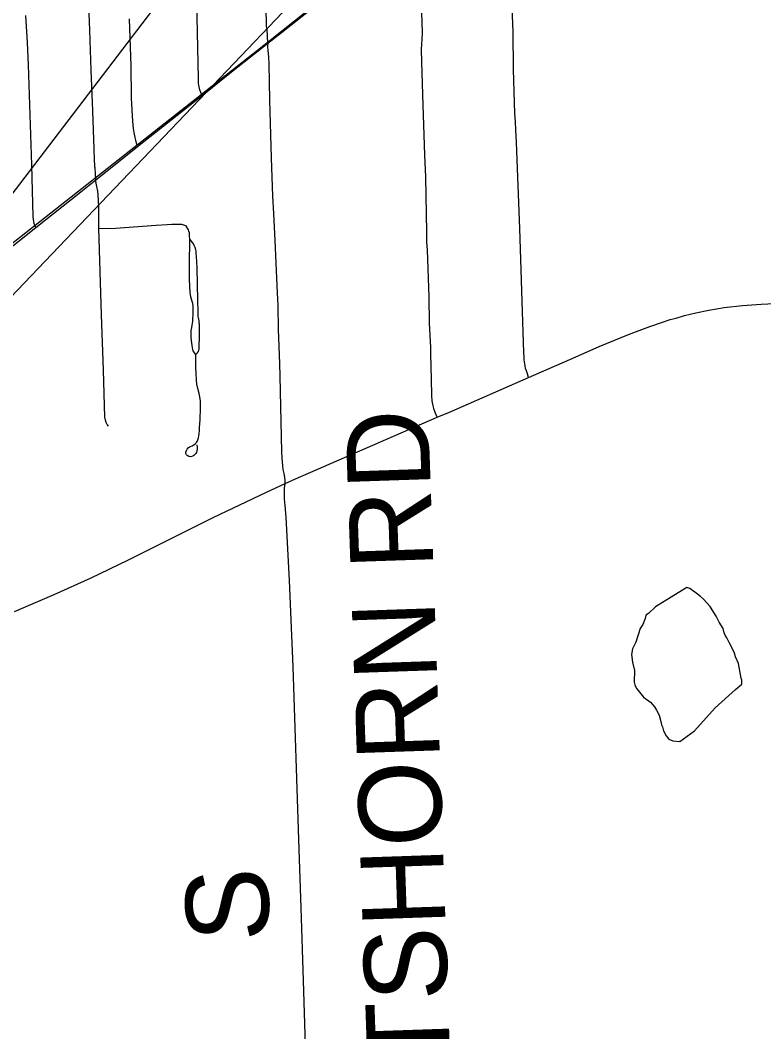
# Model space of a CAD drawing. Extents: x -12 to 34, y 0 to 22.
# Drawn here: x 5.489 to 5.999, y 17.363 to 18.055 of the extents above; entities that cross this region are included whole.
import ezdxf

# ---------------------------------------------------------------- set-up
doc = ezdxf.new("R2010")
doc.units = 0
for name, color, linetype in [('GM_X_Adjacent_County', 7, 'Continuous'), ('GM_X_Corporation', 7, 'Continuous'), ('GM_X_County_Road_Text', 7, 'Continuous'), ('GM_X_Major_Lake', 7, 'Continuous'), ('GM_X_Major_River', 7, 'Continuous'), ('GM_X_Minor_Lake', 7, 'Continuous'), ('GM_X_Township', 7, 'Continuous')]:
    doc.layers.add(name, color=color, linetype=linetype)

msp = doc.modelspace()

# ---------------------------------------------------------------- linework, layer by layer
at = {"layer": 'GM_X_Adjacent_County'}
msp.add_lwpolyline([(6.62656, 19.06353), (5.2189, 17.58992), (6.62656, 19.43297)], close=True, dxfattribs=at)
msp.add_lwpolyline([(6.62656, 19.06353), (5.2189, 17.58992), (6.62656, 19.43297)], dxfattribs=at)
at = {"layer": 'GM_X_Corporation'}
msp.add_lwpolyline([(4.21516, 16.89608), (4.31222, 16.96474), (4.74688, 17.31604), (5.03809, 17.55354), (5.18709, 17.66982), (5.65945, 18.04091), (6.05453, 18.35511), (6.09781, 18.38665), (6.1312, 18.40211), (6.16953, 18.40953), (6.55349, 18.44232), (6.69012, 18.44788), (6.85026, 18.4485), (6.9294, 18.45221), (7.10746, 18.45407), (7.25585, 18.4584), (7.28615, 18.45159), (7.37827, 18.44726), (7.7344, 18.45716)], dxfattribs=at)
at = {"layer": 'GM_X_Major_Lake'}
msp.add_lwpolyline([(5.48538, 17.65081), (5.51247, 17.66238), (5.53791, 17.6739), (5.56308, 17.68603), (5.6215, 17.71513), (5.65797, 17.73256), (5.67079, 17.73837), (5.6778, 17.74155), (5.77495, 17.7837), (5.78329, 17.78732), (5.83754, 17.811), (5.86588, 17.82338), (5.88581, 17.83215), (5.90598, 17.8404), (5.92058, 17.84578), (5.92934, 17.84893), (5.93456, 17.85054), (5.93854, 17.85166), (5.94425, 17.85328), (5.95207, 17.85526), (5.96089, 17.857), (5.97145, 17.85875), (5.98399, 17.86012), (5.99673, 17.86113), (6.01539, 17.86198)], dxfattribs=at)
at = {"layer": 'GM_X_Major_River'}
for points in [[(5.6138, 18.004), (5.613, 18.00601), (5.61224, 18.0079), (5.61179, 18.00994), (5.61148, 18.01213), (5.61133, 18.01575), (5.6102, 18.06809), (5.60906, 18.0943), (5.60861, 18.12307), (5.60785, 18.15109), (5.60812, 18.16528), (5.60807, 18.16778), (5.60797, 18.16906), (5.60782, 18.17047), (5.60767, 18.17128), (5.60685, 18.17419)], [(5.54104, 17.94627), (5.54055, 17.95442), (5.54044, 17.95523), (5.54031, 17.95631), (5.54008, 17.95974), (5.53984, 17.9674), (5.53901, 17.99349), (5.53783, 18.02133), (5.53688, 18.04859), (5.53522, 18.09473), (5.53415, 18.12199), (5.53309, 18.13958), (5.53262, 18.15043), (5.53203, 18.16459)], [(5.65896, 18.03985), (5.66821, 18.04715), (5.70212, 18.07407), (5.71558, 18.08475)], [(5.65896, 18.03985), (5.65837, 18.04945), (5.65809, 18.05126), (5.65789, 18.05507), (5.65722, 18.07213), (5.65689, 18.08202)], [(5.83754, 17.811), (5.83667, 17.81348), (5.83598, 17.81545), (5.83549, 17.81712), (5.8351, 17.819), (5.8347, 17.82156), (5.83451, 17.82314), (5.83441, 17.82472), (5.83431, 17.82807), (5.83302, 17.86286), (5.83252, 17.88474), (5.83144, 17.91283), (5.82917, 17.97186), (5.82887, 17.98034), (5.82847, 17.98586), (5.82798, 17.99167), (5.82729, 18.02184), (5.82689, 18.04746), (5.82583, 18.07583)], [(5.77495, 17.7837), (5.77383, 17.78647), (5.77331, 17.78777), (5.77267, 17.78946), (5.77228, 17.79089), (5.77188, 17.79271), (5.77149, 17.79492), (5.77124, 17.79869), (5.77098, 17.80974), (5.77058, 17.8269), (5.77045, 17.83171), (5.77006, 17.83964), (5.76967, 17.84835), (5.76941, 17.8659), (5.76824, 17.89839), (5.76784, 17.90359), (5.76784, 17.91049), (5.76706, 17.94805), (5.76641, 17.96339), (5.76537, 17.99732), (5.76438, 18.02694), (5.76422, 18.03539), (5.76487, 18.04644), (5.76471, 18.05472), (5.76422, 18.06431)], [(5.49987, 17.91358), (5.49894, 17.91639), (5.49853, 17.91761), (5.49829, 17.91908), (5.49812, 17.92111), (5.49715, 17.95645), (5.496, 17.99081), (5.4949, 18.02494), (5.49426, 18.04021), (5.49317, 18.05874)], [(5.56958, 17.96894), (5.56892, 17.97138), (5.5684, 17.97332), (5.56794, 17.97511), (5.56727, 17.9787), (5.5669, 17.98131), (5.56668, 17.98385), (5.56645, 17.98639), (5.56599, 17.99387), (5.56542, 18.00236), (5.56533, 18.02458), (5.56514, 18.03055), (5.56411, 18.0565)], [(5.6138, 18.004), (5.63408, 18.02021), (5.65896, 18.03985)], [(5.67079, 17.73837), (5.67077, 17.74033), (5.67049, 17.74265), (5.67005, 17.74515), (5.66944, 17.74802), (5.66907, 17.75063), (5.66883, 17.75328), (5.66864, 17.75583), (5.66848, 17.76009), (5.66735, 17.8118), (5.66706, 17.82028), (5.66659, 17.83248), (5.66621, 17.84382), (5.66592, 17.8603), (5.66573, 17.86488), (5.66554, 17.86859), (5.66391, 17.90471), (5.66296, 17.92319), (5.66239, 17.93501), (5.66152, 17.96121), (5.66037, 18.00085), (5.6598, 18.02572), (5.65952, 18.0302), (5.65914, 18.03487), (5.65894, 18.03725), (5.65896, 18.03812), (5.65901, 18.03898), (5.65896, 18.03985)], [(5.56958, 17.96894), (5.60977, 18.00079), (5.6138, 18.004)], [(5.54104, 17.94627), (5.54883, 17.9525), (5.56958, 17.96894)], [(5.49987, 17.91358), (5.53082, 17.93809), (5.54104, 17.94627)], [(5.54315, 17.91313), (5.54303, 17.92799), (5.54267, 17.93602), (5.54244, 17.93838), (5.54173, 17.94156), (5.54112, 17.94498), (5.54104, 17.94627)], [(5.47765, 17.89598), (5.48073, 17.89842), (5.49987, 17.91358)], [(5.54315, 17.91313), (5.54536, 17.9129), (5.55458, 17.91324), (5.58243, 17.91517), (5.58993, 17.91561), (5.59312, 17.9158), (5.5955, 17.91586), (5.59875, 17.91592), (5.59986, 17.9158), (5.60122, 17.91547), (5.60239, 17.91493), (5.60326, 17.91411)], [(5.54965, 17.77754), (5.54882, 17.77872), (5.54823, 17.78013), (5.54764, 17.78166), (5.54729, 17.78379), (5.54623, 17.81601), (5.54492, 17.85377), (5.54315, 17.91313)], [(5.60544, 17.90558), (5.60534, 17.90795), (5.60526, 17.90901), (5.60513, 17.91004), (5.60488, 17.91116), (5.60452, 17.91212), (5.60398, 17.91314), (5.60326, 17.91411)], [(5.60956, 17.82679), (5.60871, 17.82775), (5.60822, 17.82844), (5.60785, 17.82929), (5.60759, 17.83014), (5.6071, 17.83286), (5.60668, 17.83627), (5.60647, 17.83834), (5.60636, 17.84021), (5.60636, 17.84164), (5.60642, 17.8431), (5.60673, 17.84521), (5.60716, 17.84681), (5.60754, 17.84932), (5.60785, 17.85569), (5.60785, 17.85873), (5.60771, 17.86002), (5.60746, 17.8615), (5.60697, 17.86298), (5.60658, 17.86455), (5.6061, 17.86622), (5.60586, 17.86774), (5.6057, 17.86917), (5.6053, 17.87794), (5.6052, 17.8938), (5.60536, 17.89984), (5.60544, 17.90558)], [(5.60956, 17.82679), (5.61046, 17.82759), (5.6111, 17.82844), (5.61153, 17.82935), (5.61179, 17.83036), (5.6119, 17.83163), (5.61195, 17.83366), (5.61201, 17.83717), (5.61198, 17.84133), (5.61205, 17.84542), (5.61203, 17.84658), (5.61199, 17.84745), (5.61191, 17.84816), (5.61176, 17.84962), (5.61156, 17.85088), (5.61148, 17.85155), (5.61127, 17.85282), (5.6112, 17.85418), (5.6111, 17.85576), (5.61098, 17.86389), (5.61053, 17.88564), (5.61029, 17.89065), (5.60989, 17.89595), (5.6097, 17.89732), (5.6095, 17.89838), (5.60904, 17.89995), (5.60851, 17.90127), (5.60792, 17.90232), (5.6072, 17.90338), (5.60641, 17.90449), (5.60544, 17.90558)], [(5.61029, 17.76489), (5.6105, 17.76323), (5.61051, 17.76183), (5.61021, 17.76072), (5.60992, 17.75972), (5.60951, 17.75896), (5.60893, 17.75821), (5.60828, 17.75757), (5.60753, 17.75704), (5.60601, 17.75675), (5.60467, 17.75686), (5.60367, 17.75745), (5.60309, 17.75809), (5.6028, 17.75896), (5.6028, 17.7599), (5.60309, 17.76101), (5.60362, 17.76194), (5.60437, 17.76276), (5.60525, 17.76346), (5.60589, 17.76381), (5.607, 17.76428), (5.60811, 17.76492), (5.60928, 17.76574), (5.61004, 17.76643), (5.61046, 17.7672), (5.61104, 17.76838), (5.61132, 17.76965), (5.61155, 17.77099), (5.61184, 17.77262), (5.61208, 17.77449), (5.61219, 17.77682), (5.61264, 17.78197), (5.61281, 17.79019), (5.6127, 17.79479), (5.61226, 17.79764), (5.61183, 17.80005), (5.61084, 17.80344), (5.61029, 17.8064), (5.60996, 17.80925), (5.60974, 17.81396), (5.60952, 17.81779), (5.60952, 17.82217), (5.60956, 17.82679)], [(5.68609, 17.30951), (5.68344, 17.39832), (5.68167, 17.44809), (5.68002, 17.49475), (5.6762, 17.61296), (5.67385, 17.67202), (5.67138, 17.71525), (5.67069, 17.72332), (5.67031, 17.72798), (5.6702, 17.73148), (5.67041, 17.73513), (5.67079, 17.73837)]]:
    msp.add_lwpolyline(points, dxfattribs=at)
at = {"layer": 'GM_X_Minor_Lake'}
for points in [[(5.94593, 17.66722), (5.92434, 17.65391), (5.91973, 17.64942), (5.91781, 17.64831), (5.9174, 17.64603), (5.91582, 17.64188), (5.91389, 17.63925), (5.91109, 17.62979), (5.90875, 17.62527), (5.90794, 17.62148), (5.90862, 17.61615), (5.91005, 17.61044), (5.90993, 17.60247), (5.91028, 17.60056), (5.91065, 17.59942), (5.91176, 17.59788), (5.91623, 17.59212), (5.91773, 17.59096), (5.9211, 17.58863), (5.92371, 17.58556), (5.9252, 17.58326), (5.92704, 17.57982), (5.92812, 17.57562), (5.92846, 17.57334), (5.9292, 17.57181), (5.92992, 17.56914), (5.93176, 17.5657), (5.93363, 17.56339)], [(5.94593, 17.66722), (5.92434, 17.65391), (5.91973, 17.64942), (5.91781, 17.64831), (5.9174, 17.64603), (5.91582, 17.64188), (5.91389, 17.63925), (5.91109, 17.62979), (5.90875, 17.62527), (5.90794, 17.62148), (5.90862, 17.61615), (5.91005, 17.61044), (5.90993, 17.60247), (5.91028, 17.60056), (5.91065, 17.59942), (5.91176, 17.59788), (5.91623, 17.59212), (5.91773, 17.59096), (5.9211, 17.58863), (5.92371, 17.58556), (5.9252, 17.58326), (5.92704, 17.57982), (5.92812, 17.57562), (5.92846, 17.57334), (5.9292, 17.57181), (5.92992, 17.56914), (5.93176, 17.5657), (5.93363, 17.56339), (5.93626, 17.56221), (5.94119, 17.56176), (5.95115, 17.56922), (5.96542, 17.58497), (5.97925, 17.5973), (5.98348, 17.60104), (5.98352, 17.6037), (5.98316, 17.60522), (5.98141, 17.61512), (5.9792, 17.61971), (5.97848, 17.62238), (5.97664, 17.6262), (5.9748, 17.62965), (5.97333, 17.63271), (5.97222, 17.63462), (5.97148, 17.63615), (5.97077, 17.6392), (5.96817, 17.64341), (5.96596, 17.64762), (5.96337, 17.65183), (5.96189, 17.65414), (5.95965, 17.65683), (5.95741, 17.65914), (5.95516, 17.66107), (5.95329, 17.66261), (5.94804, 17.66649), (5.94593, 17.66722)], [(5.93363, 17.56339), (5.93626, 17.56221), (5.94119, 17.56176), (5.95115, 17.56922), (5.96542, 17.58497), (5.97925, 17.5973), (5.98348, 17.60104), (5.98352, 17.6037), (5.98316, 17.60522), (5.98141, 17.61512), (5.9792, 17.61971), (5.97848, 17.62238), (5.97664, 17.6262), (5.9748, 17.62965), (5.97333, 17.63271), (5.97222, 17.63462), (5.97148, 17.63615), (5.97077, 17.6392), (5.96817, 17.64341), (5.96596, 17.64762), (5.96337, 17.65183), (5.96189, 17.65414), (5.95965, 17.65683), (5.95741, 17.65914), (5.95516, 17.66107), (5.95329, 17.66261), (5.94804, 17.66649), (5.94593, 17.66722)]]:
    msp.add_lwpolyline(points, dxfattribs=at)
at = {"layer": 'GM_X_Township'}
msp.add_lwpolyline([(5.48538, 17.65081), (5.51247, 17.66238), (5.53791, 17.6739), (5.56308, 17.68603), (5.6215, 17.71513), (5.65797, 17.73256), (5.67079, 17.73837), (5.6778, 17.74155), (5.77495, 17.7837), (5.78329, 17.78732), (5.83754, 17.811), (5.86588, 17.82338), (5.88581, 17.83215), (5.90598, 17.8404), (5.92058, 17.84578), (5.92934, 17.84893), (5.93456, 17.85054), (5.93854, 17.85166), (5.94425, 17.85328), (5.95207, 17.85526), (5.96089, 17.857), (5.97145, 17.85875), (5.98399, 17.86012), (5.99673, 17.86113), (6.01539, 17.86198)], dxfattribs=at)

# ---------------------------------------------------------------- texts
at = {"layer": 'GM_X_County_Road_Text'}
for s, height, rotation, p in [('HARTSHORN RD', 0.0568182, 91.94462, (5.78942, 17.17831)), ('S', 0.05682, 91.2447, (5.66007, 17.42534))]:
    msp.add_text(s, height=height, rotation=rotation, dxfattribs=at).set_placement(p)

doc.saveas('drawing.dxf')
